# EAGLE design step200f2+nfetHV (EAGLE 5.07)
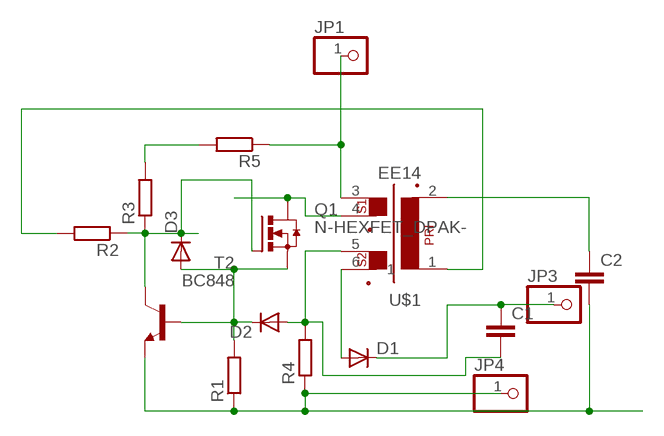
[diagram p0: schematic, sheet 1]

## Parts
C1  C-EU025-025X050  [C025-025X050]
C2  C-EUC0805  [C0805]
D1  DIODE-SMA-DO214  [SMA-DO214AC]
D2  DIODE-MINIMELF  [MINIMELF]
D3  DIODE-MINIMELF  [MINIMELF]
JP1  PINHD-1X11MM6  [1X1MM8]
JP3  PINHD-1X11MM6  [1X1MM8]
JP4  PINHD-1X11MM6  [1X1MM8]
Q1  N-HEXFET_DPAK-  [TO252]
R1  R-EU_R0805  [R0805]
R2  R-EU_R0805  [R0805]
R3  R-EU_R1206  [R1206]
R4  R-EU_R0805  [R0805]
R5  R-EU_R1206  [R1206]
T2  BC848  [SOT23]
U$1  EE14  [EE14]

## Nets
A: D1.A U$1.6
B1C2: D3.C Q1.1(G) R2.1 R3.1 T2.C
C1: Q1.3(D) U$1.4
EB: D2.C D3.A Q1.2(S) R1.2 T2.B
N$1: R3.2 R5.2
N$4: R2.2 U$1.1
N$6: C2.1 U$1.2
NDOT: C1.2 D2.A R4.2 U$1.5
V+: JP1.1 R5.1 U$1.3
V-: C2.2 JP4.1 R1.1 R4.1 T2.E
VOUT+: C1.1 D1.K(C) JP3.1

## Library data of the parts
C1 C2 = rcl:C-EU: CAPACITOR, European symbol
D1-D3 = diode:DIODE-: DIODE
JP1 JP3 JP4 = pinhead:PINHD-1X1: PIN HEADER
Q1 = transistor-power:N-HEXFET_?-*: HEXFET® Power MOSFET
R1-R5 = rcl:R-EU_: RESISTOR, European symbol
T2 = transistor:BC848: NPN TRANSISTOR
U$1 = trafo:EE14

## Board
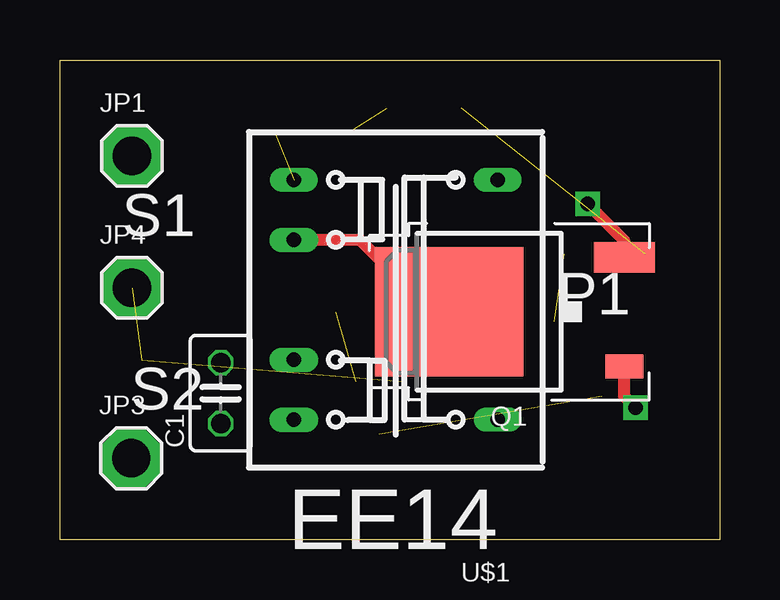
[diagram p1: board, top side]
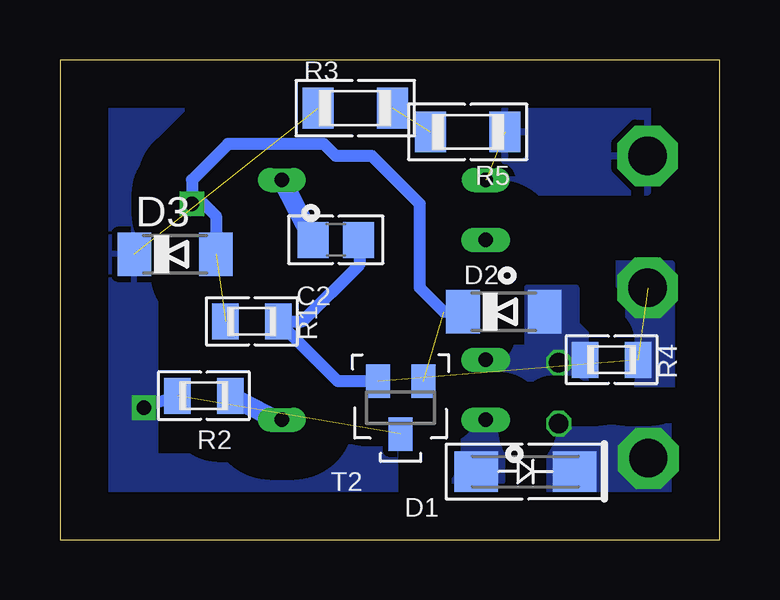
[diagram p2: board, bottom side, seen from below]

Size 27.5 x 20 mm. Coordinates in mm from the lower left corner, seen from the top.
Outline: 0,20 27.5,20 27.5,0 0,0 0,20
Copper layers (1*16): Top 0.035mm / dielectric 1.5mm / Bottom 0.035mm
Design rules "default *": minimum track width 10mil, minimum drill 20mil, track to track 8mil, track to pad 8mil, pad to pad 8mil, via to via 8mil, smd to smd 8mil, copper to edge 40mil, drill to drill 8mil, minimum pad ring 1mil, minimum via ring 8mil, stop-mask expansion 4mil, vias tented up to drill 0mil, thermal gap 10mil

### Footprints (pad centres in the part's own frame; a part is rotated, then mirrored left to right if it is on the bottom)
C025-025X050 = drill 0.813 octagon: 1 -1.27,0; 2 1.27,0
C0805 = smd 1.3 x 1.5: 1 -0.95,0; 2 0.95,0
SMA-DO214AC = smd 1.8 x 1.7: A 2.05,-0.127; K -2.05,-0.127
MINIMELF = smd 1.4 x 1.8: A 1.7,0; C -1.7,0
1X1MM8 = drill 1.6 pad 2.54 octagon: 1 0,0
TO252 = smd 1 x 1.6: 1 -2.28,-3.53 | smd 1.27 x 2.54: 2 2.28,-3.53 | smd 5.4 x 6.2: 3 0,3.77
R0805 = smd 1.1 x 1.5: 1 -1.1,0; 2 1.1,0
R1206 = smd 1.3 x 1.7: 1 -1.55,0; 2 1.55,0
SOT23 = smd 1 x 1.4: B -0.95,-1.1; C 0,1.1; E 0.95,-1.1
EE14 = drill 0.6 pad 1 long: 1 4.25,-5; 2 4.25,5; 3 -4.25,5 | drill 0.6 pad 1.016 long: 4 -4.25,2.5; 5 -4.25,-2.5; 6 -4.25,-5

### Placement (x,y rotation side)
C1  6.7,6.11 90 top
C2  16,12.5 0 bottom
D1  8.1,2.71 180 bottom
D2  9,9.5 0 bottom
D3  22.7,11.9 0 bottom
JP1  3,16 0 top
JP3  2.97,3.39 0 top
JP4  3,10.5 0 top
Q1  20,9.5 90 top
R1  19.5,9.1 180 bottom
R2  21.5,6 0 bottom
R3  15.19,17.99 0 bottom
R4  4.5,7.5 180 bottom
R5  10.5,17 180 bottom
T2  13.3,5.5 180 bottom
U$1  14,10 0 top

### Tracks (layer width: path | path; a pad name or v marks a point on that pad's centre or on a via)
A
  pour Bottom (isolate 2, rank 3, no thermals): 9,5 11.5,5 12,4.5 12,2.5 9,2.5
B1C2  (via drill 0.6)  (2 unrouted)
  Top 0.5: Q1.1 23.53,5.97 v24,5.5
  Bottom 0.5: v24,5.5 24.1,5.5 R2.1
  pour Bottom (isolate 2, rank 3): 15.5,19 26,19 26,1 13.5,1 13.5,5.5 15,5.5 19.5,3.5 23.5,3.5 23.5,15.5 18,15.5 15.5,15.5
C1
  Top 0.5: Q1.3 15.5,9.5 12.5,12.5 U$1.4
EB  (via drill 0.6)  (2 unrouted)
  Top 0.5: Q1.2 23.53,12.47 v22,14
  Bottom 0.5: D3.A 21,13.5 21.5,14 v22,14 22,15 20.5,16.5 16.5,16.5 16,16 14.5,16 12.5,14 12.5,10.5 11.5,9.5 D2.C
N$1  (1 unrouted)
N$4
  Bottom 0.8: R2.2 18.5,5 U$1.1
N$6
  Bottom 0.8: C2.1 U$1.2
NDOT
  pour Bottom (isolate 1.5, rank 3, no thermals): 5,8 5,7 5.5,6.5 10,6.5 10.5,7 10.5,7.5 10,8 8,8 8,10.5 6,10.5 6,9
V+  (1 unrouted)
  pour Bottom (isolate 2, rank 4): 3,19.5 9.5,19.5 9.1,17.4 9.1,16.4 10,15.5 10.5,14.5 3,14.5
V-  (2 unrouted)
  Bottom 0.5: T2.E 15.9,6.6 R1.1 17.4,9.1 15,11.5 15,12.45 C2.2
  pour Bottom (isolate 1.5, rank 4, no thermals): 2,11.5 4.5,11.5 5,11 5,9.5 4,8.5 4,6 2,6
VOUT+
  pour Bottom (isolate 2, rank 3, no thermals): 2,5 7,5 7.5,4.5 7.5,1 2,1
